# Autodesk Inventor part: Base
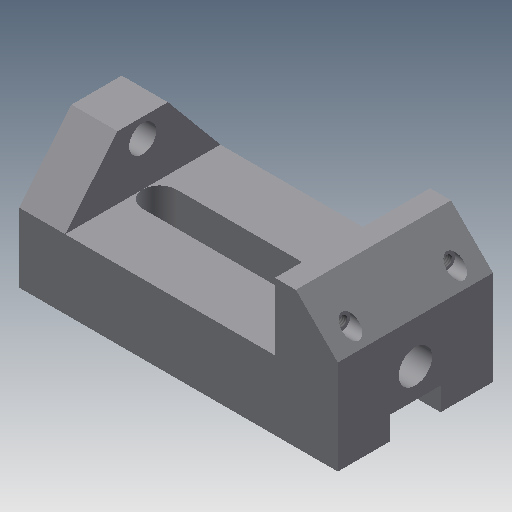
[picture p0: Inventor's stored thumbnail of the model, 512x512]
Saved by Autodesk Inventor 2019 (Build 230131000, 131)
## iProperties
Shininess: 77.0
Length Units: 11269
Angle Units: 11279
Time Units: 11290
Mass Units: 11283
Length Display Precision: 3
Angle Display Precision: 2
Created: 2002-02
Part Number: Base
Document SubType Name: Modeling
Designer: ***
Density: 1 g/cm^3
Material: Generic
Appearance: Default
Density: 0.0
Volumn: 0.0
Area: 0.0
PropertySet Name: Model Information
Control State: 0
Master: False
Checked Out: False
Author: ***
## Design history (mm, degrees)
sketch "Sketch2"
  geometry: L1 (-63.961, -4.254)-(-63.961, -37.254); L2 (-63.961, -37.254)-(88.039, -37.254); L3 (88.039, -37.254)-(88.039, 7.746); L4 (88.039, 7.746)-(68.039, 27.746); L5 (68.039, 27.746)-(58.039, 27.746); L6 (58.039, 27.746)-(58.039, -4.254); L7 (58.039, -4.254)-(-63.961, -4.254)
  constraints: 14 end point, 4 parallel, 1 perpendicular, 1 vertical
  dimensions: "d7" = 10 distance of L4.end L5.end; "d8" = 135 deg angle of L3 L4; "d9" = 33 distance of L1.start L1.end; "d10" = 152 distance of L1.end L2.end; "d11" = 65 distance between parallel lines of L5 L2; "d21" = 30 distance between parallel lines of L3 L6
extrude "Extrusion1" new body sketch "Sketch2" stored distance "d13" = 74; taper "d14" = 0 deg
sketch "Sketch3"
  geometry: L1 (0, 74)-(0, 0) reference; L2 (0, 0)-(-30, 25); L3 (-30, 25)-(-30, 49); L4 (-30, 49)-(0, 74); C1 r 6.5 at (-21, 37)
  constraints: 6 end point, 1 centre point, 1 equal length, 1 parallel
  dimensions: "d15" = 24 distance of L2.end L3.end; "d16" = 30 distance between parallel lines of L3 L1; "d17" = 13 diameter of C1; "d18" = 9 distance from line of L3 C1.centre
extrude "Extrusion2" join sketch "Sketch3" distance "d19" = 22; taper "d20" = 0 deg
sketch "Sketch4"
  geometry: L1 (0, 0)-(0, 74) reference; L2 (0, 0)-(45, 0) reference; C1 r 8 at (25, 37)
  constraints: 1 centre point
  dimensions: "d22" = 16 diameter of C1; "d23" = 25 distance from line of L1 C1.centre; "d24" = 37 distance from line of L2 C1.centre
extrude "Extrusion3" cut sketch "Sketch4" distance "d25" = 13; taper "d26" = 0 deg
sketch "Sketch5"
  geometry: L1 (45, 74)-(0, 74) reference; L2 (65, 0)-(65, 74) reference; 1 further point
  dimensions: "d27" = 12 distance from line of point (51, 62) L1; "d28" = 14 distance from line of L2 point (51, 62)
hole "Hole1" sketch "Sketch5" at (51, 62) diameter "d29" = 4.917; stored, may be unused: countersink angle "d33" = 82 deg, drill point angle "d35" = 0 deg; dims "d30" = 12, "d31" = 8, "d32" = 10, "d34" = 45
mirror "Mirror1"
sketch "Sketch6"
  geometry: L1 (100, 0)-(100, 74) reference; L2 (100, 74)-(0, 74) reference; L3 (14, 45)-(92, 45); L4 (92, 29)-(14, 29); A1 r 8 centre (92, 37) between (92, 29) and (92, 45); A2 r 8 centre (14, 37) between (14, 45) and (14, 29)
  constraints: 4 end point, 4 point on circle, 4 tangent, 2 centre point, 1 horizontal, 1 parallel
  dimensions: "d36" = 8 radius of A2; "d37" = 78 distance of L4.start L4.end; "d38" = 8 distance from line of L1 A1.centre; "d39" = 37 distance from line of L2 A2.centre
extrude "Extrusion4" cut sketch "Sketch6" extent not by distance; stored distance "d40" = 13; taper "d41" = 0 deg
sketch "Sketch7"
  geometry: L1 (45, 74)-(0, 74) reference; L2 (11, 49)-(0, 49); L3 (0, 49)-(0, 25); L4 (0, 25)-(11, 25); L5 (11, 25)-(11, 49); L6 (0, 0)-(45, 0) reference; L7 (0, 0)-(0, 74) reference
  constraints: 8 end point, 2 parallel, 1 collinear, 1 horizontal, 1 perpendicular
  dimensions: "d47" = 11 distance of L3.end L4.end; "d48" = 25 distance between parallel lines of L6 L4; "d49" = 24 distance of L2.end L3.end
extrude "Extrusion5" cut sketch "Sketch7" extent not by distance; stored distance "d45" = 13; taper "d46" = 0 deg
body "Solid1"
